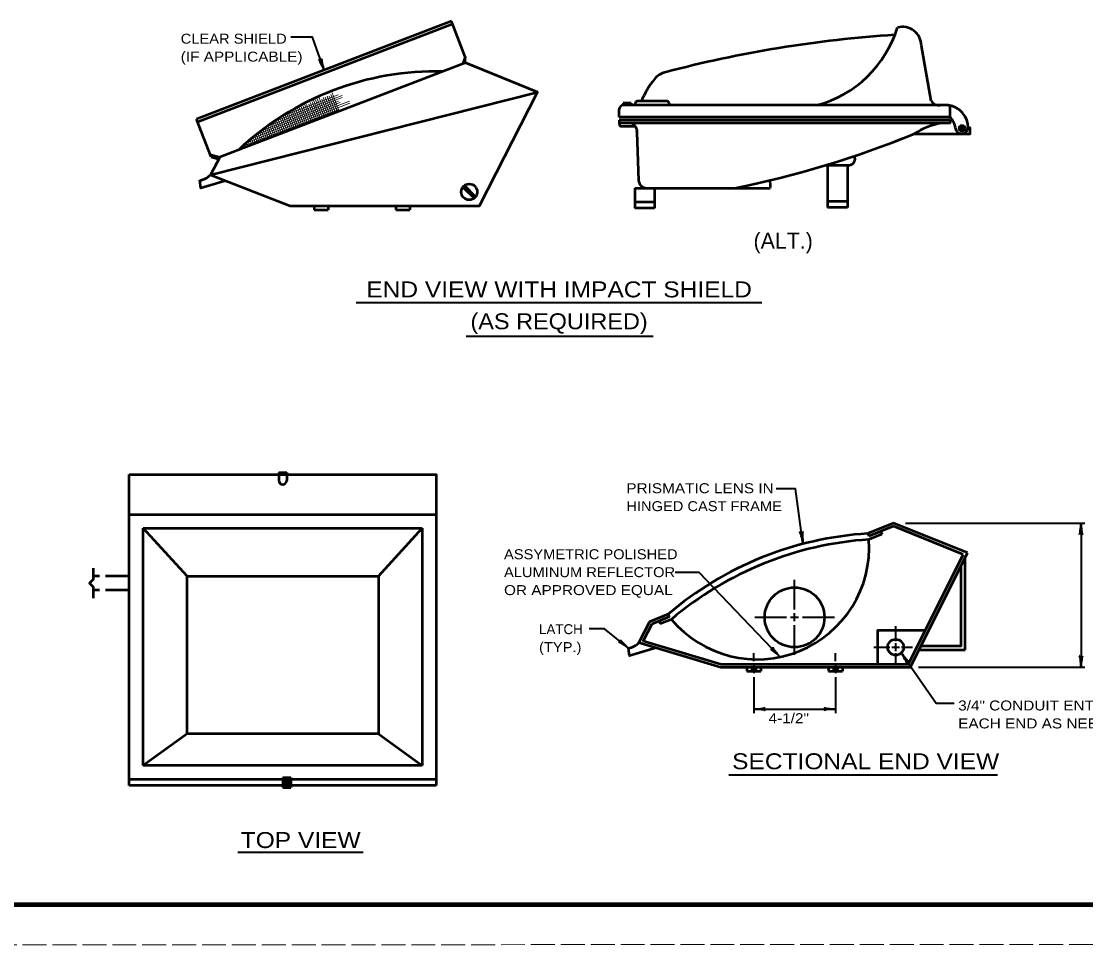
# Model space of a CAD drawing. Extents: x -67 to 613, y -55 to 385.
# Drawn here: x 119.2 to 386.2, y -55.5 to 176 of the extents above; entities that cross this region are included whole.
import ezdxf
from ezdxf.enums import TextEntityAlignment as Align

# ---------------------------------------------------------------- set-up
doc = ezdxf.new("R2010")
doc.units = 0
doc.linetypes.add('LONG_DASHED', pattern=[7.5, 6, -1.5])
doc.layers.add('1', color=7, linetype='Continuous', lineweight=13)
doc.layers.add('61', color=7, linetype='Continuous', lineweight=35)

msp = doc.modelspace()

# ---------------------------------------------------------------- hatches: boundary and pattern name
at = {"layer": '1'}
msp.add_hatch(color=256, dxfattribs=at).paths.add_polyline_path([(354.431, 149.183, 1), (355.931, 149.183, 1)])

# ---------------------------------------------------------------- linework, layer by layer
at = {"layer": '1', "lineweight": 53}
for p, q in [((227.114, 176.041), (163.164, 151.493)), ((227.383, 175.341), (163.433, 150.792)), ((230.519, 167.172), (227.114, 176.041)), ((347.414, 156.072), (344.983, 169.859)), ((230.519, 167.172), (229.948, 165.346)), ((230.519, 167.172), (230.383, 165.513)), ((166.626, 137.525), (248.67, 158.287)), ((270.194, 155.493), (270.194, 154.993)), ((272.194, 155.493), (270.194, 155.493)), ((351.694, 154.993), (270.194, 154.993)), ((270.694, 155.493), (270.694, 154.993)), ((271.694, 155.493), (271.694, 154.993)), ((272.194, 155.493), (272.194, 154.993)), ((273.194, 155.493), (273.194, 154.993)), ((281.194, 155.993), (273.694, 155.993)), ((281.694, 155.493), (281.694, 154.993)), ((269.194, 151.993), (269.194, 153.993)), ((352.194, 151.993), (352.194, 154.493)), ((166.793, 142.04), (163.164, 151.493)), ((352.194, 151.993), (269.194, 151.993)), ((352.194, 151.243), (269.194, 151.243)), ((269.194, 151.243), (269.194, 150.243)), ((352.001, 150.493), (269.194, 150.493)), ((269.694, 149.743), (273.194, 149.743)), ((273.634, 148.22), (274.055, 136.159)), ((166.569, 142.624), (168.973, 141.94)), ((166.793, 142.04), (168.837, 141.459)), ((320.933, 139.956), (326.933, 139.956)), ((321.435, 139.969), (321.435, 129.343)), ((326.435, 139.969), (326.435, 129.343)), ((229.986, 134.495), (232.792, 131.689)), ((230.34, 134.849), (233.146, 132.043)), ((273.053, 134.228), (307.053, 134.228)), ((273.053, 134.228), (273.053, 129.228)), ((278.053, 134.228), (278.053, 129.228)), ((326.435, 130.843), (321.435, 130.843)), ((192.642, 129.775), (192.642, 128.775)), ((192.642, 128.775), (196.142, 128.775)), ((196.142, 129.775), (196.142, 128.775)), ((213.142, 129.775), (213.142, 128.775)), ((213.142, 128.775), (216.642, 128.775)), ((216.642, 129.775), (216.642, 128.775)), ((278.053, 130.728), (273.053, 130.728)), ((278.053, 129.228), (273.053, 129.228)), ((326.435, 129.343), (321.435, 129.343)), ((146.292, -15.581), (146.292, 62.419)), ((183.792, 62.919), (185.792, 62.919)), ((183.792, 62.919), (183.792, 60.919)), ((185.792, 62.919), (185.792, 60.919)), ((146.292, 52.419), (223.292, 52.419)), ((149.792, 48.919), (219.792, 48.919)), ((149.792, -10.581), (149.792, 48.919)), ((160.792, 36.919), (149.792, 48.919)), ((208.792, 36.919), (219.792, 48.919)), ((219.792, 48.919), (219.792, -10.581)), ((338.007, 50.235), (331.516, 47.612)), ((338.007, 49.426), (331.797, 46.917)), ((334.761, 48.115), (335.042, 47.419)), ((356.55, 42.742), (338.007, 50.235)), ((355.487, 42.363), (338.007, 49.426)), ((331.516, 47.612), (331.797, 46.917)), ((335.042, 47.419), (331.819, 46.117)), ((342.272, 14.105), (356.55, 42.742)), ((341.772, 14.855), (355.487, 42.363)), ((355.949, 18.474), (355.949, 41.537)), ((137.292, 36.169), (137.292, 38.919)), ((160.792, -2.581), (160.792, 36.919)), ((160.792, 36.919), (208.792, 36.919)), ((208.792, 36.919), (208.792, -2.581)), ((137.292, 31.419), (137.292, 34.169)), ((281.448, 27.384), (276.812, 25.511)), ((281.448, 27.384), (281.729, 26.688)), ((276.812, 25.511), (274.134, 20.255)), ((281.729, 26.688), (277.353, 24.92)), ((279.208, 25.669), (279.489, 24.974)), ((282.269, 26.098), (279.489, 24.974)), ((274.134, 20.255), (294.662, 14.105)), ((344.45, 18.474), (355.949, 18.474)), ((294.772, 14.855), (341.772, 14.855)), ((301.162, 14.105), (301.162, 13.105)), ((302.412, 14.105), (302.412, 13.105)), ((303.412, 14.105), (303.412, 13.105)), ((304.662, 14.105), (304.662, 13.105)), ((321.662, 14.105), (321.662, 13.105)), ((322.912, 14.105), (322.912, 13.105)), ((323.912, 14.105), (323.912, 13.105)), ((325.162, 14.105), (325.162, 13.105)), ((301.162, 13.105), (304.662, 13.105)), ((321.662, 13.105), (325.162, 13.105)), ((160.792, -2.581), (149.792, -10.581)), ((208.792, -2.581), (160.792, -2.581)), ((208.792, -2.581), (219.792, -10.581)), ((219.792, -10.581), (149.792, -10.581)), ((184.792, -14.081), (146.292, -14.081)), ((184.792, -15.581), (146.292, -15.581)), ((184.792, -13.581), (184.792, -16.081)), ((184.792, -13.581), (186.792, -13.581)), ((186.792, -14.228), (184.792, -14.228)), ((184.792, -14.831), (186.792, -14.831)), ((186.792, -15.454), (184.792, -15.454)), ((186.792, -13.581), (186.792, -16.081)), ((223.292, -14.081), (186.792, -14.081)), ((223.292, -15.581), (186.792, -15.581)), ((184.792, -16.081), (186.792, -16.081))]:
    msp.add_line(p, q, dxfattribs=at)
at = {"layer": '1'}
for p, q in [((198.698, 157.635), (184.39, 152.142)), ((198.487, 153.272), (196.802, 157.659)), ((198.954, 153.451), (197.162, 158.117)), ((201.627, 155.546), (175.665, 145.58)), ((201.535, 156.046), (176.789, 146.547)), ((199.2, 155.685), (178.005, 147.549)), ((198.759, 156.051), (179.334, 148.595)), ((199.704, 156.95), (180.806, 149.696)), ((199.651, 157.465), (182.466, 150.868)), ((191.485, 150.584), (189.749, 155.105)), ((191.952, 150.763), (190.221, 155.272)), ((192.419, 150.942), (190.779, 155.213)), ((192.886, 151.121), (191.285, 155.291)), ((193.352, 151.301), (191.655, 155.721)), ((193.819, 151.48), (192.144, 155.841)), ((194.286, 151.659), (192.518, 156.263)), ((194.753, 151.838), (193.021, 156.349)), ((195.219, 152.018), (193.444, 156.64)), ((195.686, 152.197), (193.912, 156.818)), ((194.562, 156.52), (196.154, 152.374)), ((196.62, 152.555), (194.927, 156.963)), ((197.087, 152.734), (195.437, 157.03)), ((197.553, 152.914), (195.881, 157.269)), ((198.02, 153.093), (196.418, 157.266)), ((198.872, 153.953), (174.62, 144.643)), ((186.351, 148.612), (184.877, 152.451)), ((186.818, 148.791), (185.309, 152.72)), ((187.284, 148.971), (185.742, 152.986)), ((187.751, 149.15), (186.177, 153.249)), ((188.218, 149.329), (186.613, 153.508)), ((188.685, 149.508), (187.051, 153.764)), ((189.151, 149.688), (187.489, 154.016)), ((189.618, 149.867), (187.929, 154.265)), ((190.085, 150.046), (188.371, 154.511)), ((190.552, 150.225), (188.813, 154.753)), ((191.018, 150.404), (189.372, 154.691)), ((181.683, 146.82), (180.629, 149.566)), ((182.15, 146.999), (181.047, 149.87)), ((182.617, 147.178), (181.467, 150.171)), ((183.083, 147.357), (181.889, 150.469)), ((183.55, 147.537), (182.312, 150.762)), ((184.017, 147.716), (182.736, 151.052)), ((184.484, 147.895), (183.161, 151.339)), ((184.951, 148.074), (183.588, 151.622)), ((185.417, 148.254), (184.016, 151.902)), ((185.884, 148.433), (184.446, 152.178)), ((177.949, 145.386), (177.33, 146.998)), ((178.416, 145.565), (177.737, 147.332)), ((178.882, 145.744), (178.146, 147.662)), ((179.349, 145.924), (178.556, 147.989)), ((179.816, 146.103), (178.968, 148.312)), ((180.283, 146.282), (179.381, 148.631)), ((180.75, 146.461), (179.795, 148.946)), ((181.216, 146.641), (180.211, 149.258)), ((174.682, 144.131), (174.52, 144.552)), ((175.148, 144.31), (174.917, 144.913)), ((175.615, 144.49), (175.315, 145.27)), ((176.082, 144.669), (175.715, 145.624)), ((176.549, 144.848), (176.117, 145.973)), ((177.015, 145.027), (176.52, 146.319)), ((177.482, 145.207), (176.924, 146.66))]:
    msp.add_line(p, q, dxfattribs=at)
at = {"layer": '1', "lineweight": 40}
for p, q in [((203.172, 105.503), (304.969, 105.503)), ((230.784, 97.127), (277.701, 97.127)), ((296.639, -12.872), (364.031, -12.872)), ((173.475, -32.238), (204.966, -32.238))]:
    msp.add_line(p, q, dxfattribs=at)
at = {"layer": '1', "lineweight": 35}
for p, q in [((341.007, 50.235), (386.007, 50.235)), ((385.007, 50.235), (385.007, 14.105)), ((313.162, 28.605), (313.162, 36.039)), ((313.162, 25.605), (313.162, 27.605)), ((303.162, 26.605), (311.162, 26.605)), ((312.162, 26.605), (314.162, 26.605)), ((313.162, 17.17), (313.162, 24.605)), ((315.162, 26.605), (323.162, 26.605)), ((338.522, 20.605), (338.522, 24.355)), ((333.022, 19.105), (337.022, 19.105)), ((337.522, 19.105), (339.522, 19.105)), ((338.522, 18.105), (338.522, 20.105)), ((340.022, 19.105), (342.711, 19.105)), ((302.912, 15.605), (302.912, 17.605)), ((323.412, 15.605), (323.412, 17.605)), ((338.522, 14.487), (338.522, 17.605)), ((302.912, 14.605), (302.912, 12.605)), ((323.412, 14.605), (323.412, 12.605)), ((344.272, 14.105), (386.007, 14.105)), ((302.912, 11.605), (302.912, 2.605)), ((323.412, 11.605), (323.412, 2.605)), ((302.912, 3.605), (323.412, 3.605))]:
    msp.add_line(p, q, dxfattribs=at)
at = {"layer": '1', "linetype": 'LONG_DASHED', "lineweight": 53}
for p, q in [((146.292, 36.919), (137.292, 36.919)), ((146.292, 33.419), (137.292, 33.419))]:
    msp.add_line(p, q, dxfattribs=at)
at = {"layer": '1', "lineweight": 35}
for points in [[(195.139, 163.767), (192.234, 172.024), (186.803, 172.024)], [(315.252, 45.225), (313.356, 58.844), (308.531, 58.844)], [(309.392, 16.78), (289.229, 37.812), (283.197, 37.812)], [(271.507, 18.902), (265.446, 23.676), (261.655, 23.676)], [(339.936, 17.69), (348.685, 5.057), (353.219, 5.057)]]:
    msp.add_lwpolyline(points, dxfattribs=at)
at = {"layer": '1', "lineweight": 53}
for points in [[(230.59, 165.592), (168.973, 141.94), (166.626, 137.525), (186.642, 129.775)], [(186.642, 129.775), (234.142, 129.775), (248.67, 158.287), (230.59, 165.592)], [(343.177, 147.796), (357.177, 147.796), (357.177, 149.296), (356.677, 149.296)], [(170.392, 136.067), (164.243, 134.187), (163.999, 136.172)], [(146.292, 62.419), (223.292, 62.419), (223.292, -15.581)], [(344.949, 19.474), (354.949, 19.474), (354.949, 39.531)], [(137.292, 36.169), (136.292, 35.169), (137.292, 34.169)], [(277.353, 24.92), (275.211, 20.715), (294.772, 14.855)], [(334.022, 14.855), (334.022, 23.355), (346.01, 23.355)], [(278.445, 18.963), (271.751, 16.916), (271.507, 18.902)], [(294.662, 14.105), (304.662, 14.105), (321.662, 14.105), (342.272, 14.105)]]:
    msp.add_lwpolyline(points, dxfattribs=at)
for centre, radius in [((355.181, 149.183), 0.75), ((231.566, 133.269), 2), ((313.162, 26.605), 7.5), ((338.522, 19.105), 2)]:
    msp.add_circle(centre, radius, dxfattribs=at)
for centre, radius, start, end in [((311.212, 183.068), 29.055, 284.92173, 342.79873), ((340.191, 169.843), 4.792, 0.19246, 104.79651), ((357.619, -127.3), 300.55, 93.67629, 104.84466), ((223.12, 91.572), 71.894, 88.51089, 133.48892), ((281.899, 158.385), 5, 104.84466, 140.99248), ((295.326, 147.51), 22.279, 140.99248, 157.61013), ((270.194, 153.993), 1, 90, 180), ((273.694, 155.493), 0.5, 90, 180), ((281.194, 155.493), 0.5, 0, 90), ((349.379, 157.276), 2.304, 211.49396, 277.85492), ((351.694, 154.493), 0.5, 0, 90), ((351.061, 149.411), 5.618, 358.82226, 83.52776), ((269.694, 150.243), 0.5, 180, 270), ((271.585, 148.49), 2.066, 352.48021, 78.08915), ((352.486, 134.225), 16.457, 98.68489, 124.44911), ((351.68, 150.975), 0.58, 303.67651, 27.52118), ((349.012, 148.762), 4.534, 7.71166, 45.43592), ((248.296, 381.542), 252.269, 281.3757, 292.09308), ((355.093, 149.412), 1.588, 181.5054, 355.77977), ((326.771, 141.504), 1.557, 275.97169, 28.28809), ((163.36, 140.64), 4.513, 278.13941, 316.35785), ((276.054, 136.228), 2, 182.00024, 270), ((304.987, 134.904), 2.175, 341.89746, 34.76046), ((184.792, 60.935), 1, 180.93011, 359.06989), ((336.818, -37.586), 85.363, 93.5609, 130.4391), ((303.792, 44.157), 28.096, 220.00037, 3.9997), ((337.391, -39.003), 85.302, 93.74496, 130.25504), ((270.868, 23.37), 4.513, 278.13941, 316.35785)]:
    msp.add_arc(centre, radius, start, end, dxfattribs=at)
at = {"layer": '1', "lineweight": 40}
for centre, major_axis, ratio, start_param, end_param in [((194.516, 164.704), (0.74, -1.633), 0.122415, 0.8963533, 3.1415927), ((194.516, 164.704), (0.74, -1.633), 0.122415, 0.8963533, 3.1415927), ((194.967, 164.894), (0.417, -1.715), 0.07063, 3.1407148, 5.41811), ((194.967, 164.894), (0.417, -1.715), 0.07063, 3.1407148, 5.41811), ((315.307, 46.364), (0.068, -1.764), 0.07063, 3.1407148, 5.41811), ((384.795, 49.114), (0.176, 1.756), 0.07063, 3.1407148, 5.41811), ((384.795, 49.114), (0.176, 1.756), 0.07063, 3.1407148, 5.41811), ((385.283, 49.143), (-0.156, 1.786), 0.122415, 0.8963533, 3.1415927), ((385.283, 49.143), (-0.156, 1.786), 0.122415, 0.8963533, 3.1415927), ((314.828, 46.268), (0.401, -1.747), 0.122415, 0.8963533, 3.1415927), ((270.479, 19.36), (1.499, -0.982), 0.122415, 0.8963533, 3.1415927), ((270.479, 19.36), (1.499, -0.982), 0.122415, 0.8963533, 3.1415927), ((270.758, 19.761), (1.271, -1.225), 0.07063, 3.1407148, 5.41811), ((270.758, 19.761), (1.271, -1.225), 0.07063, 3.1407148, 5.41811), ((308.769, 17.735), (1.089, -1.389), 0.07063, 3.1407148, 5.41811), ((308.438, 17.377), (1.349, -1.181), 0.122415, 0.8963533, 3.1415927), ((340.4, 16.649), (0.856, -1.544), 0.07063, 6.2823074, 8.5597026), ((340.785, 16.951), (-1.145, 1.379), 0.122415, 0.8963533, 3.1415927), ((384.73, 15.196), (0.156, -1.786), 0.122415, 0.8963533, 3.1415927), ((385.218, 15.225), (-0.176, -1.756), 0.07063, 3.1407148, 5.41811), ((304.032, 3.393), (-1.756, 0.176), 0.07063, 3.1407148, 5.41811), ((304.032, 3.393), (-1.756, 0.176), 0.07063, 3.1407148, 5.41811), ((304.003, 3.881), (-1.786, -0.156), 0.122415, 0.8963533, 3.1415927), ((304.003, 3.881), (-1.786, -0.156), 0.122415, 0.8963533, 3.1415927), ((322.321, 3.328), (1.786, 0.156), 0.122415, 0.8963533, 3.1415927), ((322.291, 3.816), (1.756, -0.176), 0.07063, 3.1407148, 5.41811)]:
    msp.add_ellipse(centre, major_axis=major_axis, ratio=ratio, start_param=start_param, end_param=end_param, dxfattribs=at)
at = {"layer": '61', "lineweight": 158}
msp.add_line((602.101, -45.48), (-36.959, -45.46), dxfattribs=at)
at = {"layer": '61', "linetype": 'LONG_DASHED', "lineweight": 13}
msp.add_line((613.041, -55.46), (-67.019, -55.48), dxfattribs=at)

# ---------------------------------------------------------------- texts
at = {"layer": '1'}
for s, height, width, p in [('CLEAR SHIELD', 2.5, 1.1, (159.191, 170.43)), ('(IF APPLICABLE)', 2.5, 1.15, (159.191, 165.93)), ('PRISMATIC LENS IN', 2.5, 1.15, (270.961, 57.723)), ('HINGED CAST FRAME', 2.5, 1.1, (270.961, 53.223)), ('ASSYMETRIC POLISHED', 2.5, 1.1, (240.285, 41.174)), ('ALUMINUM REFLECTOR', 2.5, 1.1, (240.285, 36.674)), ('OR APPROVED EQUAL', 2.5, 1.15, (240.285, 32.174)), ('(TYP.)', 2.5, 1.1, (249.074, 17.883)), ('3/4" CONDUIT ENTRY HOLE', 2.5, 1.15, (354.2, 3.247)), ('4-1/2"', 2.5, 1.15, (306.635, 0.058)), ('EACH END AS NEEDED', 2.5, 1.15, (354.2, -1.253)), ('SECTIONAL END VIEW', 4, 1.15, (297.501, -11.492)), ('TOP VIEW', 4, 1.15, (174.243, -31.242))]:
    msp.add_text(s, height=height, dxfattribs=dict(at, width=width)).set_placement(p)
for s, height, p in [('(ALT.)', 4, (302.873, 119.038)), ('LATCH', 2.5, (249.074, 22.383))]:
    msp.add_text(s, height=height, dxfattribs=at).set_placement(p)
for s, width, p in [('END VIEW WITH IMPACT SHIELD', 1.15, (254.095, 106.824)), ('(AS REQUIRED)', 1.1, (254.095, 98.824))]:
    msp.add_text(s, height=4, dxfattribs=dict(at, width=width)).set_placement(p, align=Align.CENTER)

doc.saveas('drawing.dxf')
